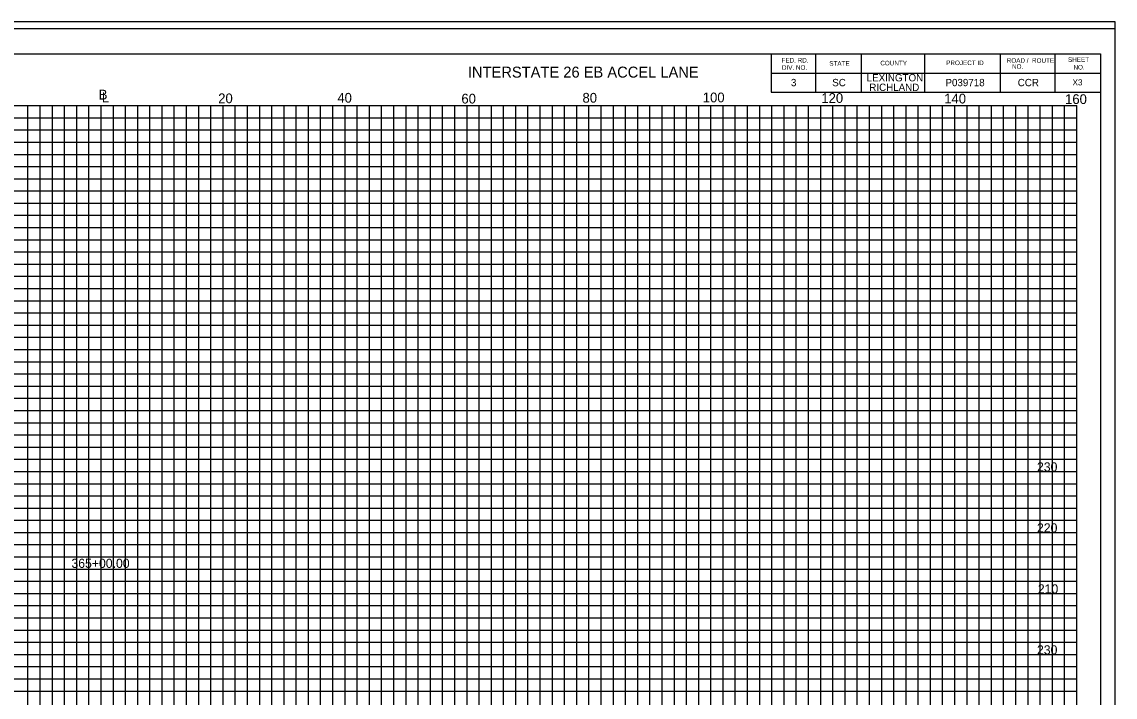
# Model space of a CAD drawing. Extents: x 967 to 1326, y 964 to 1744.
# Drawn here: x 1147 to 1326.3, y 1633 to 1743.7 of the extents above; entities that cross this region are included whole.
import ezdxf

# ---------------------------------------------------------------- set-up
doc = ezdxf.new("R2010")
doc.units = 0
for name, color, linetype in [('Default', 7, 'Continuous'), ('RD_SHT_Bndy', 7, 'Continuous'), ('RD_SHT_IplotShp', 7, 'Continuous'), ('RD_SHT_MjGrid', 7, 'Continuous'), ('RD_SHT_MnGrid', 7, 'Continuous'), ('RD_SHT_TX', 7, 'Continuous'), ('RD_Sketch1', 7, 'Continuous')]:
    doc.layers.add(name, color=color, linetype=linetype)

msp = doc.modelspace()

# ---------------------------------------------------------------- linework, layer by layer
at = {"layer": 'RD_SHT_Bndy'}
for p, q in [((996.11, 1738.46), (1323.89, 1738.46)), ((1269.89, 1738.46), (1269.89, 1732.21)), ((1277.14, 1738.46), (1277.14, 1732.21)), ((1284.64, 1738.46), (1284.64, 1732.21)), ((1295, 1738.46), (1295, 1732.21)), ((1307.43, 1738.46), (1307.43, 1732.21)), ((1316.39, 1738.46), (1316.39, 1732.21)), ((1323.89, 1738.46), (1323.89, 1528.98)), ((1269.89, 1735.33), (1323.89, 1735.33)), ((1269.89, 1732.21), (1323.89, 1732.21))]:
    msp.add_line(p, q, dxfattribs=at)
at = {"layer": 'RD_SHT_IplotShp'}
for points in [[(967.41, 1523.72), (1326.28, 1523.72), (1326.28, 1743.72), (967.41, 1743.72)], [(988.52, 1524.84), (1326.28, 1524.84), (1326.28, 1742.6), (988.52, 1742.6)]]:
    msp.add_lwpolyline(points, close=True, dxfattribs=at)
at = {"layer": 'RD_SHT_MjGrid'}
for p, q in [((1000, 1730), (1320, 1730)), ((1150, 1560), (1150, 1730)), ((1160, 1560), (1160, 1730)), ((1170, 1560), (1170, 1730)), ((1180, 1560), (1180, 1730)), ((1190, 1560), (1190, 1730)), ((1200, 1560), (1200, 1730)), ((1210, 1560), (1210, 1730)), ((1220, 1560), (1220, 1730)), ((1230, 1560), (1230, 1730)), ((1240, 1560), (1240, 1730)), ((1250, 1560), (1250, 1730)), ((1260, 1560), (1260, 1730)), ((1270, 1560), (1270, 1730)), ((1280, 1560), (1280, 1730)), ((1290, 1560), (1290, 1730)), ((1300, 1560), (1300, 1730)), ((1310, 1560), (1310, 1730)), ((1320, 1560), (1320, 1730)), ((1000, 1720), (1320, 1720)), ((1000, 1710), (1320, 1710)), ((1000, 1700), (1320, 1700)), ((1000, 1690), (1320, 1690)), ((1000, 1680), (1320, 1680)), ((1000, 1670), (1320, 1670)), ((1000, 1660), (1320, 1660)), ((1000, 1650), (1320, 1650)), ((1000, 1640), (1320, 1640))]:
    msp.add_line(p, q, dxfattribs=at)
at = {"layer": 'RD_SHT_MnGrid'}
for p, q in [((1148, 1560), (1148, 1730)), ((1152, 1560), (1152, 1730)), ((1154, 1560), (1154, 1730)), ((1156, 1560), (1156, 1730)), ((1158, 1560), (1158, 1730)), ((1162, 1560), (1162, 1730)), ((1164, 1560), (1164, 1730)), ((1166, 1560), (1166, 1730)), ((1168, 1560), (1168, 1730)), ((1172, 1560), (1172, 1730)), ((1174, 1560), (1174, 1730)), ((1176, 1560), (1176, 1730)), ((1178, 1560), (1178, 1730)), ((1182, 1560), (1182, 1730)), ((1184, 1560), (1184, 1730)), ((1186, 1560), (1186, 1730)), ((1188, 1560), (1188, 1730)), ((1192, 1560), (1192, 1730)), ((1194, 1560), (1194, 1730)), ((1196, 1560), (1196, 1730)), ((1198, 1560), (1198, 1730)), ((1202, 1560), (1202, 1730)), ((1204, 1560), (1204, 1730)), ((1206, 1560), (1206, 1730)), ((1208, 1560), (1208, 1730)), ((1212, 1560), (1212, 1730)), ((1214, 1560), (1214, 1730)), ((1216, 1560), (1216, 1730)), ((1218, 1560), (1218, 1730)), ((1222, 1560), (1222, 1730)), ((1224, 1560), (1224, 1730)), ((1226, 1560), (1226, 1730)), ((1228, 1560), (1228, 1730)), ((1232, 1560), (1232, 1730)), ((1234, 1560), (1234, 1730)), ((1236, 1560), (1236, 1730)), ((1238, 1560), (1238, 1730)), ((1242, 1560), (1242, 1730)), ((1244, 1560), (1244, 1730)), ((1246, 1560), (1246, 1730)), ((1248, 1560), (1248, 1730)), ((1252, 1560), (1252, 1730)), ((1254, 1560), (1254, 1730)), ((1256, 1560), (1256, 1730)), ((1258, 1560), (1258, 1730)), ((1262, 1560), (1262, 1730)), ((1264, 1560), (1264, 1730)), ((1266, 1560), (1266, 1730)), ((1268, 1560), (1268, 1730)), ((1272, 1560), (1272, 1730)), ((1274, 1560), (1274, 1730)), ((1276, 1560), (1276, 1730)), ((1278, 1560), (1278, 1730)), ((1282, 1560), (1282, 1730)), ((1284, 1560), (1284, 1730)), ((1286, 1560), (1286, 1730)), ((1288, 1560), (1288, 1730)), ((1292, 1560), (1292, 1730)), ((1294, 1560), (1294, 1730)), ((1296, 1560), (1296, 1730)), ((1298, 1560), (1298, 1730)), ((1302, 1560), (1302, 1730)), ((1304, 1560), (1304, 1730)), ((1306, 1560), (1306, 1730)), ((1308, 1560), (1308, 1730)), ((1312, 1560), (1312, 1730)), ((1314, 1560), (1314, 1730)), ((1316, 1560), (1316, 1730)), ((1318, 1560), (1318, 1730)), ((1000, 1728), (1320, 1728)), ((1000, 1726), (1320, 1726)), ((1000, 1724), (1320, 1724)), ((1000, 1722), (1320, 1722)), ((1000, 1718), (1320, 1718)), ((1000, 1716), (1320, 1716)), ((1000, 1714), (1320, 1714)), ((1000, 1712), (1320, 1712)), ((1000, 1708), (1320, 1708)), ((1000, 1706), (1320, 1706)), ((1000, 1704), (1320, 1704)), ((1000, 1702), (1320, 1702)), ((1000, 1698), (1320, 1698)), ((1000, 1696), (1320, 1696)), ((1000, 1694), (1320, 1694)), ((1000, 1692), (1320, 1692)), ((1000, 1688), (1320, 1688)), ((1000, 1686), (1320, 1686)), ((1000, 1684), (1320, 1684)), ((1000, 1682), (1320, 1682)), ((1000, 1678), (1320, 1678)), ((1000, 1676), (1320, 1676)), ((1000, 1674), (1320, 1674)), ((1000, 1672), (1320, 1672)), ((1000, 1668), (1320, 1668)), ((1000, 1666), (1320, 1666)), ((1000, 1664), (1320, 1664)), ((1000, 1662), (1320, 1662)), ((1000, 1658), (1320, 1658)), ((1000, 1656), (1320, 1656)), ((1000, 1654), (1320, 1654)), ((1000, 1652), (1320, 1652)), ((1000, 1648), (1320, 1648)), ((1000, 1646), (1320, 1646)), ((1000, 1644), (1320, 1644)), ((1000, 1642), (1320, 1642)), ((1000, 1638), (1320, 1638)), ((1000, 1636), (1320, 1636)), ((1000, 1634), (1320, 1634))]:
    msp.add_line(p, q, dxfattribs=at)
at = {"layer": 'RD_Sketch1'}
msp.add_lwpolyline([(967.41, 1523.72), (1326.28, 1523.72), (1326.28, 1743.72), (967.41, 1743.72)], close=True, dxfattribs=at)

# ---------------------------------------------------------------- texts
at = {"layer": 'Default'}
for s, height, p in [('X3', 1, (1319.3, 1733.3)), ('230', 1.5, (1313.47, 1670)), ('220', 1.5, (1313.47, 1660)), ('365+00.00', 1.5, (1155.13, 1654.19)), ('210', 1.5, (1313.61, 1650)), ('230', 1.5, (1313.47, 1640))]:
    msp.add_text(s, height=height, dxfattribs=at).set_placement(p)
at = {"layer": 'RD_SHT_TX'}
for s, height, p in [('FED. RD.', 0.75, (1271.58, 1737.05)), ('STATE', 0.75, (1279.41, 1736.53)), ('COUNTY', 0.75, (1287.78, 1736.59)), ('PROJECT ID', 0.75, (1298.58, 1736.63)), ('ROAD /  ROUTE', 0.75, (1308.51, 1737.01)), ('SHEET', 0.75, (1318.56, 1737.16)), ('DIV. NO.', 0.75, (1271.64, 1735.86)), ('   NO.', 0.75, (1308.51, 1736.03)), ('NO.', 0.75, (1319.45, 1735.91)), ('3', 1.2, (1273.12, 1733.17)), ('SC', 1.2, (1279.89, 1733.17)), ('LEXINGTON', 1.2, (1285.54, 1733.96)), ('P039718', 1.2, (1298.46, 1733.17)), ('CCR', 1.2, (1310.31, 1733.17)), ('B', 1.6, (1159.61, 1730.99)), ('L', 1.6, (1160.12, 1730.54)), ('20', 1.6, (1179.2, 1730.38)), ('40', 1.6, (1198.74, 1730.47)), ('60', 1.6, (1219.08, 1730.33)), ('80', 1.6, (1238.94, 1730.47)), ('100', 1.6, (1258.67, 1730.53)), ('120', 1.6, (1278.11, 1730.43)), ('RICHLAND', 1.2, (1285.97, 1732.39)), ('140', 1.6, (1298.26, 1730.34)), ('160', 1.6, (1318.08, 1730.25))]:
    msp.add_text(s, height=height, dxfattribs=at).set_placement(p)
msp.add_text('INTERSTATE 26 EB ACCEL LANE', height=1.8, rotation=0, dxfattribs=at).set_placement((1220.14, 1734.58))

doc.saveas('drawing.dxf')
